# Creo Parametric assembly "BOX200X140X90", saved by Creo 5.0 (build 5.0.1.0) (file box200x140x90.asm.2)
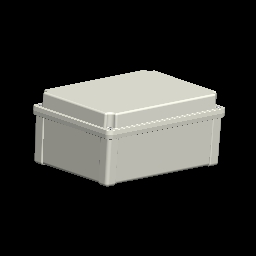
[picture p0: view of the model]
Units: millimeter Kilogram Sec (mmKs); MM, KILOGRAM, SECS

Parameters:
  MODELED_BY = " DE SANTIAGO D."
  DESCRIPTION = "CAJA  200x140x90"
  COPY_GEOM_ORIGIN_TYPE = "Part"

Created from: MSB.ASM

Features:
  1. datum plane "ASM_RIGHT"
  2. datum plane "ASM_TOP"
  3. datum plane "ASM_FRONT"
  4. coordinate system
  5. component "BOX200X140X90-BOX"
  6. component "BOX200X140X90-PLACA"
  7. component "BOX200X140X90-JUNTA"
  8. component "TORNILLO-PARKER", "PARKER-4X0_625.PRT"
  9. component "TORNILLO-PARKER", "PARKER-4X0_25.PRT"
  10. component "TORNILLO-PARKER", "PARKER-4X0_25.PRT"
  11. component "TORNILLO-PARKER", "PARKER-4X0_25.PRT"
  12. component "BOX200X140X90-TAPA"
  13. component "TORNILLO-PARKER", "PARKER-4X0_25.PRT"
  14. component "TORNILLO-PARKER", "PARKER-4X0_75.PRT"
  15. component "TORNILLO-PARKER", "PARKER-4X0_75.PRT"
  16. component "TORNILLO-PARKER", "PARKER-4X0_75.PRT"

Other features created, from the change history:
  feature "Copia 1"
  planar section "XSEC0001"
  planar section "B"

Other named items: E1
